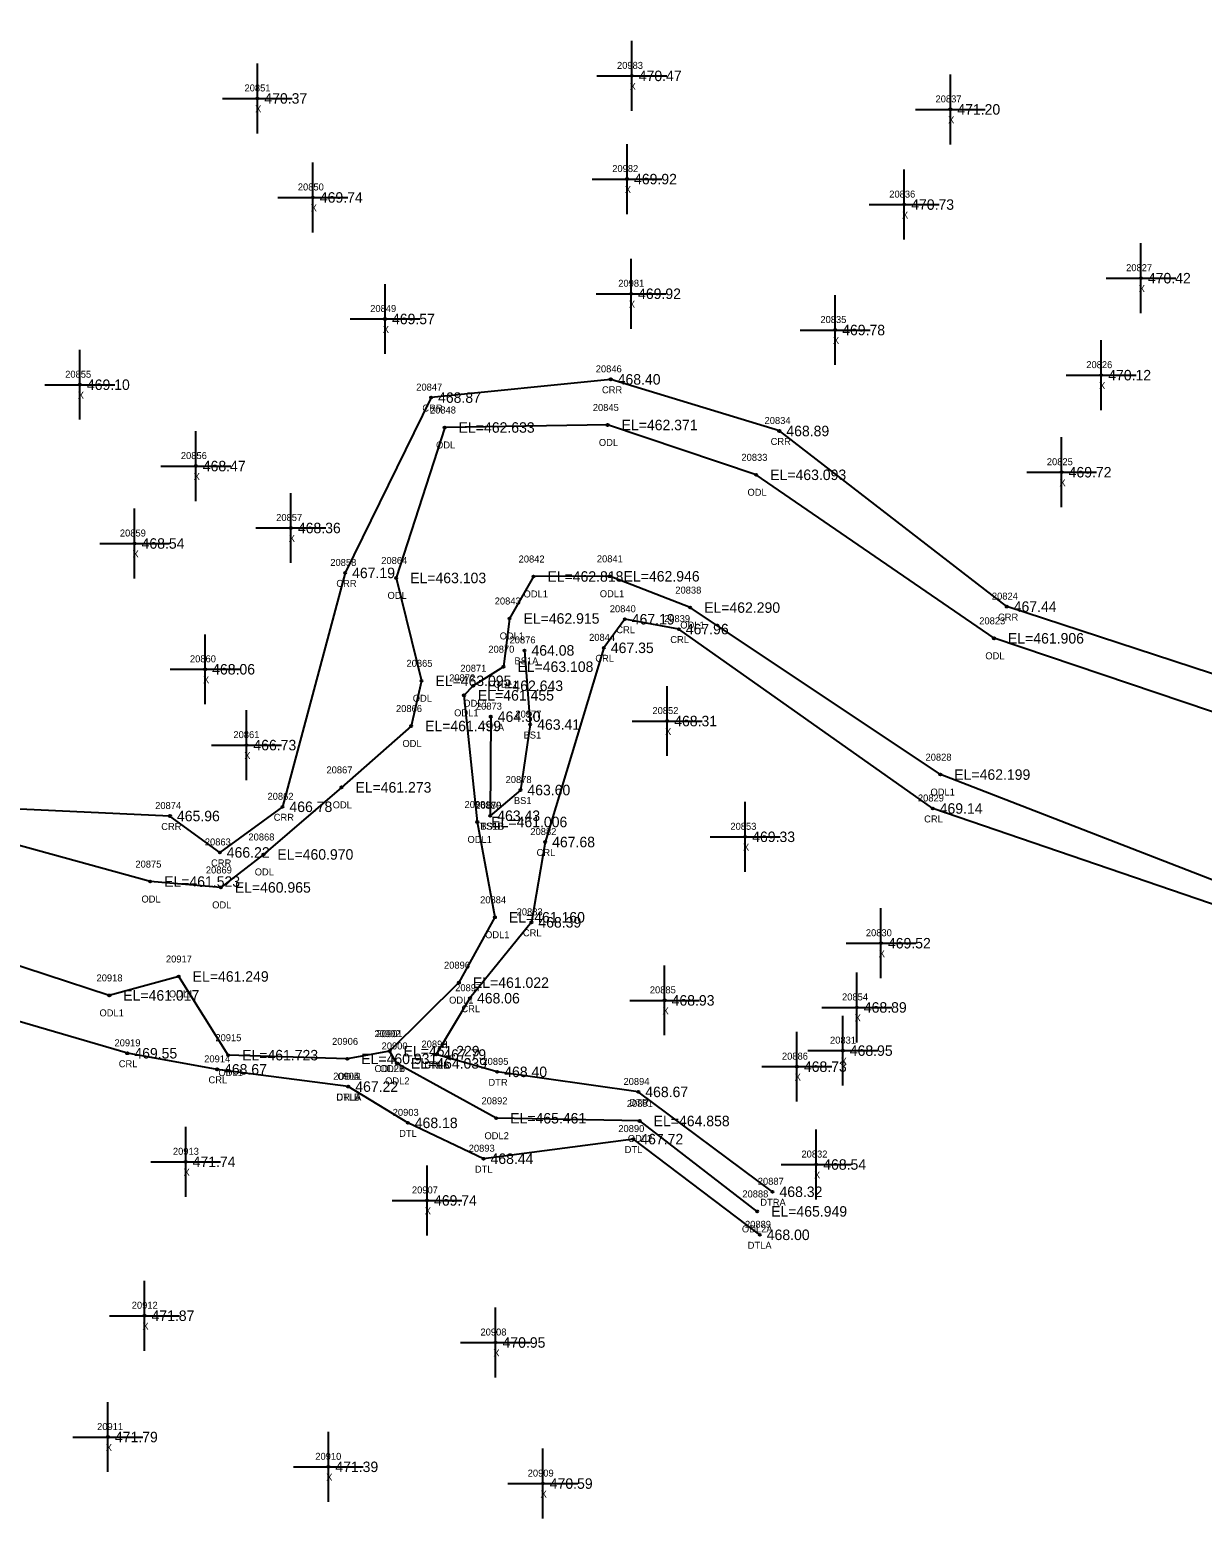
# Model space of a CAD drawing. Extents: x 1741010 to 1742139, y 749382 to 750625.
# Drawn here: x 1741246.5 to 1741414.3, y 750059.9 to 750274.5 of the extents above; entities that cross this region are included whole.
import ezdxf

# ---------------------------------------------------------------- set-up
doc = ezdxf.new("R2010")
doc.units = 0
for name, color, linetype in [('RD_DTM_BkLn2', 7, 'Continuous'), ('RD_DTM_BkLn_txCode', 7, 'Continuous'), ('RD_EX_H2O', 7, 'Continuous'), ('RD_EX_H2O_txCode', 7, 'Continuous'), ('RD_EX_Misc', 7, 'Continuous'), ('RD_EX_Misc_txCode', 7, 'Continuous'), ('RD_EX_TX_H2O_ELEV', 7, 'Continuous'), ('RD_EX_TX_Misc_ELEV', 7, 'Continuous'), ('RD_SMD_Locator', 7, 'Continuous')]:
    doc.layers.add(name, color=color, linetype=linetype)

msp = doc.modelspace()

# ---------------------------------------------------------------- linework, layer by layer
at = {"layer": 'RD_DTM_BkLn2'}
msp.add_line((1741312.45, 750176.26), (1741312.38, 750162.08), dxfattribs=at)
msp.add_lwpolyline([(1741317.28, 750185.74), (1741318.1, 750175.13), (1741316.7, 750165.76), (1741312.38, 750162.08)], dxfattribs=at)
at = {"layer": 'RD_EX_H2O'}
for points in [[(1741531.4, 750163.48), (1741496.74, 750161.28), (1741466.68, 750164.86), (1741447.36, 750172.02), (1741386.3, 750192.01), (1741353.76, 750217.14), (1741329.62, 750224.53), (1741303.91, 750221.92), (1741291.61, 750196.83), (1741282.64, 750163.36), (1741273.67, 750156.83), (1741266.54, 750162.04), (1741226.59, 750163.86), (1741212.64, 750167.03), (1741192.26, 750172.18), (1741170.42, 750180.69), (1741154.09, 750191.77), (1741121.46, 750224.58), (1741091.69, 750251.93), (1741067.74, 750274.52)], [(1741529.44, 750151.69), (1741495.88, 750157.28), (1741465.36, 750157.67), (1741446.42, 750166.61), (1741384.48, 750187.47), (1741350.45, 750210.87), (1741329.18, 750218), (1741305.86, 750217.64), (1741298.92, 750196.11), (1741302.53, 750181.39), (1741301.05, 750174.92), (1741291.08, 750166.14), (1741279.91, 750156.54), (1741273.82, 750151.82), (1741263.7, 750152.66), (1741226.75, 750162.85), (1741212.53, 750164.38), (1741190.98, 750170.64), (1741169.63, 750179.08), (1741152.49, 750189.88), (1741119.79, 750222.83), (1741091.32, 750250.11), (1741061.1, 750271.73)], [(1741292.06, 750123.32), (1741273.28, 750125.79), (1741260.44, 750128.09), (1741226.79, 750137.92), (1741206.63, 750143.28), (1741183, 750151.39), (1741159.35, 750162.36), (1741136.08, 750173.3), (1741118.23, 750196.5), (1741104.5, 750204.3), (1741081.82, 750222.56), (1741046.57, 750247.2)], [(1741521.3, 750138.92), (1741491.52, 750137.44), (1741437.22, 750144.55), (1741376.8, 750167.97), (1741340.99, 750191.87), (1741329.47, 750196.35), (1741318.56, 750196.32), (1741315.14, 750190.31), (1741314.27, 750183.41), (1741309.93, 750180.68), (1741308.62, 750179.31), (1741310.53, 750161.19), (1741313.05, 750147.55), (1741307.9, 750138.2), (1741297.98, 750128.4), (1741291.92, 750127.29), (1741274.87, 750127.82), (1741267.79, 750139.08), (1741257.86, 750136.37), (1741230.74, 750145.22)], [(1741577.19, 750059.87), (1741574.31, 750069.19), (1741563.25, 750082.19), (1741560.12, 750095.32), (1741559.96, 750109.5), (1741556.5, 750127.16), (1741554.14, 750131.7), (1741543.79, 750140.45), (1741537.22, 750131.72), (1741525.85, 750130.27), (1741518.7, 750134.1), (1741490.89, 750135.06), (1741436.94, 750142.19), (1741375.71, 750163.12), (1741339.37, 750188.79), (1741331.64, 750190.2), (1741328.64, 750186.11), (1741320.24, 750158.32), (1741318.27, 750146.83), (1741309.48, 750135.97), (1741304.66, 750127.91)], [(1741350.58, 750105.46), (1741333.77, 750118.4), (1741313.24, 750118.79), (1741299.03, 750126.64), (1741297.98, 750128.4)], [(1741352.78, 750108.27), (1741333.57, 750122.56), (1741313.38, 750125.43), (1741304.66, 750127.91)], [(1741350.96, 750102.11), (1741332.86, 750115.81), (1741311.42, 750113), (1741300.58, 750118.13), (1741292.06, 750123.32)]]:
    msp.add_lwpolyline(points, dxfattribs=at)
at = {"layer": 'RD_EX_Misc'}
for p, q in [((1741332.64, 750262.96), (1741332.64, 750272.96)), ((1741279.05, 750259.73), (1741279.05, 750269.73)), ((1741327.64, 750267.96), (1741337.64, 750267.96)), ((1741378.23, 750258.16), (1741378.23, 750268.16)), ((1741274.05, 750264.73), (1741284.05, 750264.73)), ((1741373.23, 750263.16), (1741383.23, 750263.16)), ((1741331.96, 750248.19), (1741331.96, 750258.19)), ((1741286.99, 750245.56), (1741286.99, 750255.56)), ((1741371.63, 750244.54), (1741371.63, 750254.54)), ((1741326.96, 750253.19), (1741336.96, 750253.19)), ((1741281.99, 750250.56), (1741291.99, 750250.56)), ((1741366.63, 750249.54), (1741376.63, 750249.54)), ((1741405.51, 750234.01), (1741405.51, 750244.01)), ((1741332.54, 750231.78), (1741332.54, 750241.78)), ((1741400.51, 750239.01), (1741410.51, 750239.01)), ((1741297.32, 750228.17), (1741297.32, 750238.17)), ((1741327.54, 750236.78), (1741337.54, 750236.78)), ((1741361.75, 750226.59), (1741361.75, 750236.59)), ((1741292.32, 750233.17), (1741302.32, 750233.17)), ((1741356.75, 750231.59), (1741366.75, 750231.59)), ((1741253.65, 750218.76), (1741253.65, 750228.76)), ((1741399.83, 750220.13), (1741399.83, 750230.13)), ((1741394.83, 750225.13), (1741404.83, 750225.13)), ((1741248.65, 750223.76), (1741258.65, 750223.76)), ((1741270.24, 750207.12), (1741270.24, 750217.12)), ((1741394.16, 750206.24), (1741394.16, 750216.24)), ((1741265.24, 750212.12), (1741275.24, 750212.12)), ((1741389.16, 750211.24), (1741399.16, 750211.24)), ((1741283.85, 750198.26), (1741283.85, 750208.26)), ((1741261.48, 750196.04), (1741261.48, 750206.04)), ((1741278.85, 750203.26), (1741288.85, 750203.26)), ((1741256.48, 750201.04), (1741266.48, 750201.04)), ((1741271.58, 750178.04), (1741271.58, 750188.04)), ((1741266.58, 750183.04), (1741276.58, 750183.04)), ((1741337.71, 750170.63), (1741337.71, 750180.63)), ((1741277.48, 750167.19), (1741277.48, 750177.19)), ((1741332.71, 750175.63), (1741342.71, 750175.63)), ((1741272.48, 750172.19), (1741282.48, 750172.19)), ((1741348.87, 750154.07), (1741348.87, 750164.07)), ((1741343.87, 750159.07), (1741353.87, 750159.07)), ((1741368.3, 750138.84), (1741368.3, 750148.84)), ((1741363.3, 750143.84), (1741373.3, 750143.84)), ((1741337.34, 750130.66), (1741337.34, 750140.66)), ((1741364.85, 750129.65), (1741364.85, 750139.65)), ((1741332.34, 750135.66), (1741342.34, 750135.66)), ((1741359.85, 750134.65), (1741369.85, 750134.65)), ((1741362.84, 750123.47), (1741362.84, 750133.47)), ((1741356.27, 750121.18), (1741356.27, 750131.18)), ((1741357.84, 750128.47), (1741367.84, 750128.47)), ((1741351.27, 750126.18), (1741361.27, 750126.18)), ((1741268.79, 750107.56), (1741268.79, 750117.56)), ((1741359.04, 750107.17), (1741359.04, 750117.17)), ((1741263.79, 750112.56), (1741273.79, 750112.56)), ((1741303.33, 750102.03), (1741303.33, 750112.03)), ((1741354.04, 750112.17), (1741364.04, 750112.17)), ((1741298.33, 750107.03), (1741308.33, 750107.03)), ((1741262.9, 750085.53), (1741262.9, 750095.53)), ((1741313.14, 750081.7), (1741313.14, 750091.7)), ((1741257.9, 750090.53), (1741267.9, 750090.53)), ((1741308.14, 750086.7), (1741318.14, 750086.7)), ((1741257.66, 750068.17), (1741257.66, 750078.17)), ((1741289.21, 750063.91), (1741289.21, 750073.91)), ((1741252.66, 750073.17), (1741262.66, 750073.17)), ((1741319.9, 750061.51), (1741319.9, 750071.51)), ((1741284.21, 750068.91), (1741294.21, 750068.91)), ((1741314.9, 750066.51), (1741324.9, 750066.51))]:
    msp.add_line(p, q, dxfattribs=at)
at = {"layer": 'RD_SMD_Locator'}
for centre in [(1741332.64, 750267.96), (1741279.05, 750264.73), (1741378.23, 750263.16), (1741331.96, 750253.19), (1741286.99, 750250.56), (1741371.63, 750249.54), (1741405.51, 750239.01), (1741332.54, 750236.78), (1741297.32, 750233.17), (1741361.75, 750231.59), (1741329.62, 750224.53), (1741399.83, 750225.13), (1741253.65, 750223.76), (1741303.91, 750221.92), (1741305.86, 750217.64), (1741329.18, 750218), (1741353.76, 750217.14), (1741270.24, 750212.12), (1741394.16, 750211.24), (1741350.45, 750210.87), (1741283.85, 750203.26), (1741261.48, 750201.04), (1741291.61, 750196.83), (1741298.92, 750196.11), (1741318.56, 750196.32), (1741329.47, 750196.35), (1741340.99, 750191.87), (1741386.3, 750192.01), (1741315.14, 750190.31), (1741331.64, 750190.2), (1741339.37, 750188.79), (1741384.48, 750187.47), (1741317.28, 750185.74), (1741328.64, 750186.11), (1741271.58, 750183.04), (1741314.27, 750183.41), (1741302.53, 750181.39), (1741308.62, 750179.31), (1741309.93, 750180.68), (1741301.05, 750174.92), (1741312.45, 750176.26), (1741318.1, 750175.13), (1741337.71, 750175.63), (1741277.48, 750172.19), (1741291.08, 750166.14), (1741376.8, 750167.97), (1741316.7, 750165.76), (1741266.54, 750162.04), (1741282.64, 750163.36), (1741312.38, 750162.08), (1741312.38, 750162.08), (1741375.71, 750163.12), (1741310.53, 750161.19), (1741320.24, 750158.32), (1741348.87, 750159.07), (1741273.67, 750156.83), (1741279.91, 750156.54), (1741263.7, 750152.66), (1741273.82, 750151.82), (1741313.05, 750147.55), (1741318.27, 750146.83), (1741368.3, 750143.84), (1741267.79, 750139.08), (1741307.9, 750138.2), (1741257.86, 750136.37), (1741309.48, 750135.97), (1741337.34, 750135.66), (1741364.85, 750134.65), (1741260.44, 750128.09), (1741274.87, 750127.82), (1741291.92, 750127.29), (1741297.98, 750128.4), (1741297.98, 750128.4), (1741304.66, 750127.91), (1741304.66, 750127.91), (1741362.84, 750128.47), (1741273.28, 750125.79), (1741299.03, 750126.64), (1741313.38, 750125.43), (1741356.27, 750126.18), (1741292.06, 750123.32), (1741292.06, 750123.32), (1741333.57, 750122.56), (1741313.24, 750118.79), (1741300.58, 750118.13), (1741333.77, 750118.4), (1741332.86, 750115.81), (1741268.79, 750112.56), (1741311.42, 750113), (1741359.04, 750112.17), (1741352.78, 750108.27), (1741303.33, 750107.03), (1741350.58, 750105.46), (1741350.96, 750102.11), (1741262.9, 750090.53), (1741313.14, 750086.7), (1741257.66, 750073.17), (1741289.21, 750068.91), (1741319.9, 750066.51)]:
    msp.add_circle(centre, 0.15, dxfattribs=at)

# ---------------------------------------------------------------- texts
at = {"layer": 'RD_DTM_BkLn_txCode'}
for s, p in [('20876', (1741315.14, 750186.74)), ('BS1A', (1741315.85, 750183.74)), ('20873', (1741310.33, 750177.26)), ('20877', (1741315.98, 750176.13)), ('TS1A', (1741311, 750174.26)), ('BS1', (1741317.15, 750173.13)), ('20878', (1741314.58, 750166.76)), ('20880', (1741310.22, 750163.08)), ('20879', (1741310.26, 750163.08)), ('BS1', (1741315.76, 750163.76)), ('TS1B', (1741310.95, 750160.08)), ('BS1B', (1741310.96, 750160.08))]:
    msp.add_text(s, height=1, dxfattribs=at).set_placement(p)
at = {"layer": 'RD_EX_H2O_txCode'}
for s, p in [('20846', (1741327.48, 750225.53)), ('20847', (1741301.79, 750222.92)), ('CRR', (1741328.37, 750222.53)), ('CRR', (1741302.66, 750219.92)), ('20848', (1741303.75, 750219.64)), ('20845', (1741327.06, 750220)), ('20834', (1741351.64, 750218.14)), ('ODL', (1741304.62, 750214.64)), ('ODL', (1741327.93, 750215)), ('CRR', (1741352.51, 750215.14)), ('20833', (1741348.33, 750212.87)), ('ODL', (1741349.2, 750207.87)), ('20858', (1741289.49, 750197.83)), ('20864', (1741296.78, 750198.11)), ('20842', (1741316.44, 750198.32)), ('20841', (1741327.64, 750198.35)), ('CRR', (1741290.35, 750194.83)), ('ODL', (1741297.68, 750193.11)), ('ODL1', (1741317.15, 750193.32)), ('ODL1', (1741328.06, 750193.35)), ('20838', (1741338.87, 750193.87)), ('20824', (1741384.18, 750193.01)), ('20843', (1741313.02, 750192.31)), ('20840', (1741329.49, 750191.2)), ('20839', (1741337.26, 750189.79)), ('ODL1', (1741339.58, 750188.87)), ('20823', (1741382.37, 750189.47)), ('CRR', (1741385.05, 750190.01)), ('ODL1', (1741313.73, 750187.31)), ('20844', (1741326.53, 750187.11)), ('CRL', (1741330.42, 750188.2)), ('CRL', (1741338.15, 750186.79)), ('20870', (1741312.11, 750185.41)), ('ODL', (1741383.24, 750184.47)), ('20865', (1741300.39, 750183.39)), ('20871', (1741308.1, 750182.68)), ('CRL', (1741327.42, 750184.11)), ('20872', (1741306.5, 750181.31)), ('ODL1', (1741312.86, 750180.41)), ('ODL', (1741301.29, 750178.39)), ('20866', (1741298.89, 750176.92)), ('ODL1', (1741307.21, 750176.31)), ('ODL1', (1741308.52, 750177.68)), ('ODL', (1741299.81, 750171.92)), ('20828', (1741374.68, 750169.97)), ('20867', (1741288.94, 750168.14)), ('20874', (1741264.42, 750163.04)), ('20862', (1741280.5, 750164.36)), ('ODL', (1741289.83, 750163.14)), ('20881', (1741308.7, 750163.19)), ('20829', (1741373.59, 750164.12)), ('ODL1', (1741375.39, 750164.97)), ('CRR', (1741281.39, 750161.36)), ('CRL', (1741374.48, 750161.12)), ('CRR', (1741265.29, 750160.04)), ('20882', (1741318.12, 750159.32)), ('20863', (1741271.53, 750157.83)), ('20868', (1741277.77, 750158.54)), ('ODL1', (1741309.12, 750158.19)), ('20875', (1741261.59, 750154.66)), ('CRR', (1741272.42, 750154.83)), ('CRL', (1741319.01, 750156.32)), ('20869', (1741271.68, 750153.82)), ('ODL', (1741278.67, 750153.54)), ('ODL', (1741262.46, 750149.66)), ('ODL', (1741272.58, 750148.82)), ('20884', (1741310.93, 750149.55)), ('20883', (1741316.16, 750147.83)), ('ODL1', (1741311.64, 750144.55)), ('CRL', (1741317.05, 750144.83)), ('20917', (1741265.96, 750141.08)), ('20896', (1741305.76, 750140.2)), ('20918', (1741256.03, 750138.37)), ('ODL1', (1741266.38, 750136.08)), ('ODL1', (1741306.49, 750135.2)), ('20897', (1741307.36, 750136.97)), ('ODL1', (1741256.45, 750133.37)), ('CRL', (1741308.25, 750133.97)), ('20919', (1741258.6, 750129.09)), ('20915', (1741273.04, 750129.82)), ('20906', (1741289.74, 750129.29)), ('20902', (1741295.82, 750130.4)), ('20901', (1741296.1, 750130.4)), ('20900', (1741296.83, 750128.64)), ('20898', (1741302.54, 750128.91)), ('20899', (1741302.54, 750128.91)), ('20914', (1741271.44, 750126.79)), ('20895', (1741311.26, 750126.43)), ('CRL', (1741259.21, 750126.09)), ('ODL1', (1741273.47, 750124.82)), ('20904', (1741289.9, 750124.32)), ('20905', (1741289.9, 750124.32)), ('ODL1', (1741290.51, 750124.29)), ('ODL2B', (1741295.81, 750125.4)), ('ODL1', (1741296.57, 750125.4)), ('CRLB', (1741302.96, 750125.91)), ('DTRB', (1741302.92, 750125.91)), ('CRL', (1741272.05, 750123.79)), ('ODL2', (1741297.33, 750123.64)), ('DTR', (1741312.12, 750123.43)), ('20894', (1741331.45, 750123.56)), ('CRLA', (1741290.35, 750121.32)), ('DTLB', (1741290.35, 750121.32)), ('20892', (1741311.13, 750120.79)), ('20891', (1741331.93, 750120.4)), ('DTR', (1741332.3, 750120.56)), ('20903', (1741298.42, 750119.13)), ('DTL', (1741299.34, 750116.13)), ('ODL2', (1741311.55, 750115.79)), ('20890', (1741330.71, 750116.81)), ('20893', (1741309.3, 750114)), ('DTL', (1741331.62, 750113.81)), ('ODL2', (1741332.07, 750115.4)), ('DTL', (1741310.18, 750111)), ('20887', (1741350.67, 750109.27)), ('20888', (1741348.46, 750107.46)), ('DTRA', (1741351.03, 750106.27)), ('20889', (1741348.84, 750103.11)), ('ODL2A', (1741348.4, 750102.46)), ('DTLA', (1741349.23, 750100.11))]:
    msp.add_text(s, height=1, dxfattribs=at).set_placement(p)
at = {"layer": 'RD_EX_Misc_txCode'}
for s, p in [('20983', (1741330.52, 750268.96)), ('X', (1741332.33, 750265.96)), ('20851', (1741277.21, 750265.73)), ('20837', (1741376.11, 750264.16)), ('X', (1741278.73, 750262.73)), ('X', (1741377.91, 750261.16)), ('20982', (1741329.84, 750254.19)), ('20850', (1741284.84, 750251.56)), ('X', (1741331.64, 750251.19)), ('20836', (1741369.49, 750250.54)), ('X', (1741286.68, 750248.56)), ('X', (1741371.31, 750247.54)), ('20827', (1741403.39, 750240.01)), ('20981', (1741330.7, 750237.78)), ('X', (1741405.19, 750237.01)), ('20849', (1741295.2, 750234.17)), ('X', (1741332.22, 750234.78)), ('20835', (1741359.63, 750232.59)), ('X', (1741297, 750231.17)), ('X', (1741361.43, 750229.59)), ('20826', (1741397.69, 750226.13)), ('20855', (1741251.54, 750224.76)), ('X', (1741399.52, 750223.13)), ('X', (1741253.34, 750221.76)), ('20856', (1741268.1, 750213.12)), ('20825', (1741392.04, 750212.24)), ('X', (1741269.93, 750210.12)), ('X', (1741393.84, 750209.24)), ('20857', (1741281.74, 750204.26)), ('20859', (1741259.37, 750202.04)), ('X', (1741283.54, 750201.26)), ('X', (1741261.17, 750199.04)), ('20860', (1741269.4, 750184.04)), ('X', (1741271.27, 750181.04)), ('20852', (1741335.59, 750176.63)), ('X', (1741337.4, 750173.63)), ('20861', (1741275.62, 750173.19)), ('X', (1741277.17, 750170.19)), ('20853', (1741346.75, 750160.07)), ('X', (1741348.55, 750157.07)), ('20830', (1741366.14, 750144.84)), ('X', (1741367.98, 750141.84)), ('20885', (1741335.22, 750136.66)), ('20854', (1741362.73, 750135.65)), ('X', (1741337.03, 750133.66)), ('X', (1741364.53, 750132.65)), ('20831', (1741361.01, 750129.47)), ('20886', (1741354.13, 750127.18)), ('X', (1741362.53, 750126.47)), ('X', (1741355.95, 750124.18)), ('20913', (1741266.96, 750113.56)), ('20832', (1741356.92, 750113.17)), ('X', (1741268.48, 750110.56)), ('X', (1741358.72, 750110.17)), ('20907', (1741301.17, 750108.03)), ('X', (1741303.01, 750105.03)), ('20912', (1741261.07, 750091.53)), ('X', (1741262.59, 750088.53)), ('20908', (1741310.98, 750087.7)), ('X', (1741312.82, 750084.7)), ('20911', (1741256.11, 750074.17)), ('X', (1741257.35, 750071.17)), ('20910', (1741287.34, 750069.91)), ('X', (1741288.9, 750066.91)), ('20909', (1741317.74, 750067.51)), ('X', (1741319.58, 750064.51))]:
    msp.add_text(s, height=1, dxfattribs=at).set_placement(p)
at = {"layer": 'RD_EX_TX_H2O_ELEV'}
for s, p in [('468.40', (1741330.62, 750223.78)), ('468.87', (1741304.91, 750221.17)), ('EL=462.633', (1741307.86, 750216.89)), ('EL=462.371', (1741331.18, 750217.25)), ('468.89', (1741354.76, 750216.39)), ('EL=463.093', (1741352.45, 750210.12)), ('467.19', (1741292.61, 750196.08)), ('EL=463.103', (1741300.92, 750195.36)), ('EL=462.818', (1741320.56, 750195.57)), ('EL=462.946', (1741331.47, 750195.6)), ('EL=462.290', (1741342.99, 750191.12)), ('467.44', (1741387.3, 750191.26)), ('EL=462.915', (1741317.14, 750189.56)), ('467.19', (1741332.64, 750189.45)), ('467.96', (1741340.37, 750188.04)), ('EL=461.906', (1741386.48, 750186.72)), ('467.35', (1741329.64, 750185.36)), ('EL=463.108', (1741316.27, 750182.66)), ('EL=463.095', (1741304.53, 750180.64)), ('EL=462.643', (1741311.93, 750179.93)), ('EL=461.455', (1741310.62, 750178.56)), ('EL=461.499', (1741303.05, 750174.17)), ('EL=462.199', (1741378.8, 750167.22)), ('EL=461.273', (1741293.08, 750165.39)), ('466.78', (1741283.64, 750162.61)), ('469.14', (1741376.71, 750162.37)), ('465.96', (1741267.54, 750161.29)), ('EL=461.006', (1741312.53, 750160.44)), ('466.22', (1741274.67, 750156.08)), ('467.68', (1741321.24, 750157.57)), ('EL=460.970', (1741281.91, 750155.79)), ('EL=461.523', (1741265.7, 750151.91)), ('EL=460.965', (1741275.82, 750151.07)), ('EL=461.160', (1741315.05, 750146.8)), ('468.39', (1741319.27, 750146.08)), ('EL=461.249', (1741269.79, 750138.33)), ('EL=461.022', (1741309.9, 750137.45)), ('EL=461.017', (1741259.86, 750135.62)), ('468.06', (1741310.48, 750135.22)), ('469.55', (1741261.44, 750127.34)), ('EL=461.723', (1741276.87, 750127.07)), ('EL=460.931', (1741293.92, 750126.54)), ('EL=461.229', (1741299.98, 750127.65)), ('EL=461.229', (1741299.98, 750127.65)), ('EL=464.039', (1741301.03, 750125.89)), ('467.79', (1741305.66, 750127.16)), ('467.79', (1741305.66, 750127.16)), ('468.67', (1741274.28, 750125.04)), ('468.40', (1741314.38, 750124.68)), ('467.22', (1741293.06, 750122.57)), ('467.22', (1741293.06, 750122.57)), ('468.67', (1741334.57, 750121.81)), ('468.18', (1741301.58, 750117.38)), ('EL=465.461', (1741315.24, 750118.04)), ('EL=464.858', (1741335.77, 750117.65)), ('467.72', (1741333.86, 750115.06)), ('468.44', (1741312.42, 750112.25)), ('468.32', (1741353.78, 750107.52)), ('EL=465.949', (1741352.58, 750104.71)), ('468.00', (1741351.96, 750101.36))]:
    msp.add_text(s, height=1.5, dxfattribs=at).set_placement(p)
at = {"layer": 'RD_EX_TX_Misc_ELEV'}
for s, p in [('470.47', (1741333.64, 750267.21)), ('470.37', (1741280.05, 750263.98)), ('471.20', (1741379.23, 750262.41)), ('469.92', (1741332.96, 750252.44)), ('469.74', (1741287.99, 750249.81)), ('470.73', (1741372.63, 750248.79)), ('470.42', (1741406.51, 750238.26)), ('469.92', (1741333.54, 750236.03)), ('469.57', (1741298.32, 750232.42)), ('469.78', (1741362.75, 750230.84)), ('469.10', (1741254.65, 750223.01)), ('470.12', (1741400.83, 750224.38)), ('468.47', (1741271.24, 750211.37)), ('469.72', (1741395.16, 750210.49)), ('468.36', (1741284.85, 750202.51)), ('468.54', (1741262.48, 750200.29)), ('464.08', (1741318.28, 750184.99)), ('468.06', (1741272.58, 750182.29)), ('464.30', (1741313.45, 750175.51)), ('463.41', (1741319.1, 750174.38)), ('468.31', (1741338.71, 750174.88)), ('466.73', (1741278.48, 750171.44)), ('463.60', (1741317.7, 750165.01)), ('463.43', (1741313.38, 750161.33)), ('463.43', (1741313.38, 750161.33)), ('469.33', (1741349.87, 750158.32)), ('469.52', (1741369.3, 750143.09)), ('468.93', (1741338.34, 750134.91)), ('468.89', (1741365.85, 750133.9)), ('468.95', (1741363.84, 750127.72)), ('468.73', (1741357.27, 750125.43)), ('471.74', (1741269.79, 750111.81)), ('468.54', (1741360.04, 750111.42)), ('469.74', (1741304.33, 750106.28)), ('471.87', (1741263.9, 750089.78)), ('470.95', (1741314.14, 750085.95)), ('471.79', (1741258.66, 750072.42)), ('471.39', (1741290.21, 750068.16)), ('470.59', (1741320.9, 750065.76))]:
    msp.add_text(s, height=1.5, dxfattribs=at).set_placement(p)

doc.saveas('drawing.dxf')
